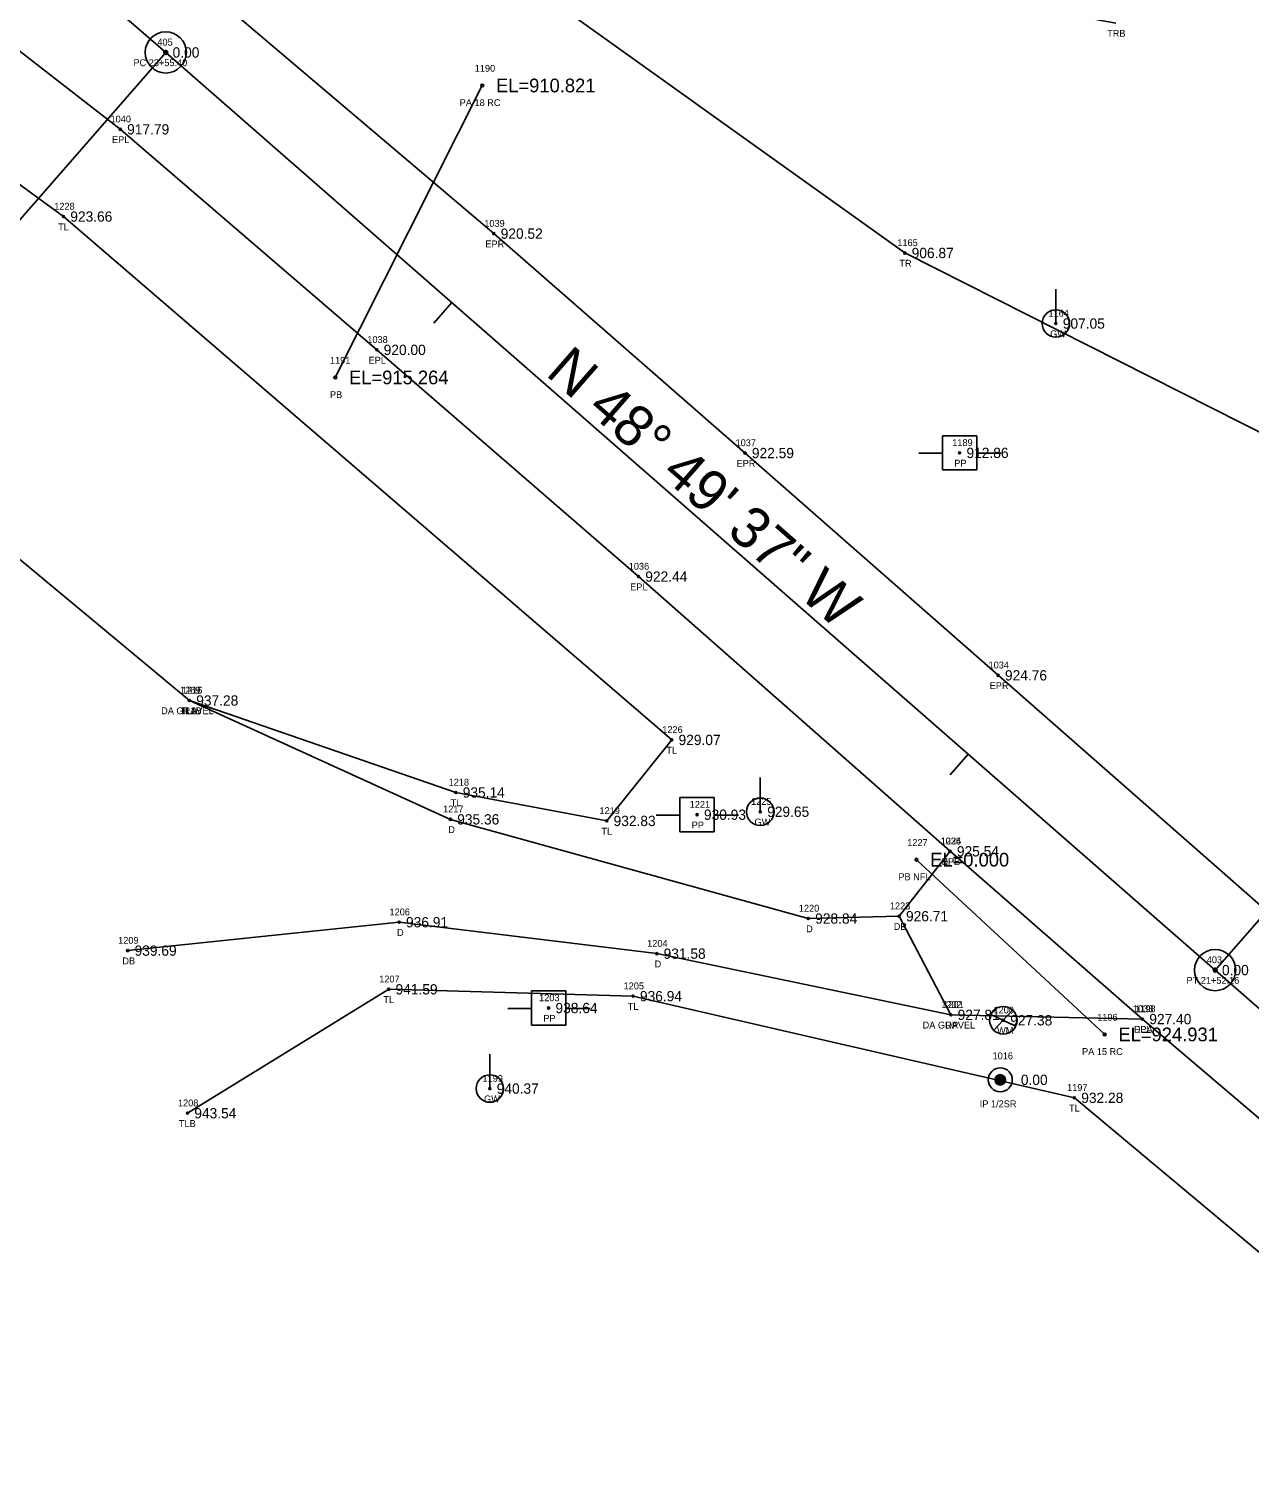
# Model space of a CAD drawing. Extents: x 1393163 to 1398407, y 1072670 to 1074651.
# Drawn here: x 1396870.8 to 1397048.8, y 1074054.9 to 1074266.9 of the extents above; entities that cross this region are included whole.
import ezdxf

# ---------------------------------------------------------------- set-up
doc = ezdxf.new("R2010")
doc.units = 0
for name, color, linetype in [('RD_EX_DR_Pipe', 7, 'Continuous'), ('RD_EX_DR_Pipe_txCode', 7, 'Continuous'), ('RD_EX_Driveway', 7, 'Continuous'), ('RD_EX_Driveway_txCode', 7, 'Continuous'), ('RD_EX_DV_Prop_txCode', 7, 'Continuous'), ('RD_EX_DV_PropPin', 7, 'Continuous'), ('RD_EX_Road', 7, 'Continuous'), ('RD_EX_Road_txCode', 7, 'Continuous'), ('RD_EX_TX_Driveway_ELEV', 7, 'Continuous'), ('RD_EX_TX_DV_Prop_ELEV', 7, 'Continuous'), ('RD_EX_TX_Road_ELEV', 7, 'Continuous'), ('RD_EX_TX_UT_ELEV', 7, 'Continuous'), ('RD_EX_TX_VEG_ELEV', 7, 'Continuous'), ('RD_EX_UT', 7, 'Continuous'), ('RD_EX_UT_txCode', 7, 'Continuous'), ('RD_EX_VEG', 7, 'Continuous'), ('RD_EX_VEG_txCode', 7, 'Continuous'), ('RD_HC_Cl', 7, 'Continuous'), ('RD_HC_Data', 7, 'Continuous'), ('RD_HC_Data_Tic', 7, 'Continuous'), ('RD_HC_Survey_ELEV', 7, 'Continuous'), ('RD_HC_txCode', 7, 'Continuous'), ('RD_SMD_Locator', 7, 'Continuous'), ('RD_TX_Pipe_ElevEX', 7, 'Continuous')]:
    doc.layers.add(name, color=color, linetype=linetype)

msp = doc.modelspace()

# ---------------------------------------------------------------- linework, layer by layer
at = {"layer": 'RD_EX_DR_Pipe'}
for p, q in [((1396936.88, 1074258.65), (1396915.45, 1074216.08)), ((1397027.62, 1074120.29), (1397000.17, 1074145.77))]:
    msp.add_line(p, q, dxfattribs=at)
at = {"layer": 'RD_EX_Driveway'}
for points in [[(1396894.17, 1074168.98), (1396932.22, 1074151.65), (1396984.41, 1074137.19), (1396997.65, 1074137.53)], [(1397033.12, 1074122.53), (1397005.18, 1074123.15), (1396997.65, 1074137.53), (1397005.07, 1074146.99)], [(1397005.18, 1074123.15), (1396962.31, 1074132.07), (1396924.76, 1074136.65), (1396885.18, 1074132.51)]]:
    msp.add_lwpolyline(points, dxfattribs=at)
at = {"layer": 'RD_EX_DV_PropPin'}
for p, q in [((1397011.77, 1074113.24), (1397011.77, 1074114.1)), ((1397011.8, 1074113.19), (1397011.8, 1074114.14)), ((1397011.84, 1074113.15), (1397011.84, 1074114.18)), ((1397011.87, 1074113.12), (1397011.87, 1074114.22)), ((1397011.91, 1074113.09), (1397011.91, 1074114.25)), ((1397011.94, 1074113.06), (1397011.94, 1074114.28)), ((1397011.98, 1074113.03), (1397011.98, 1074114.3)), ((1397012.01, 1074113.01), (1397012.01, 1074114.33)), ((1397012.05, 1074112.99), (1397012.05, 1074114.34)), ((1397012.08, 1074112.98), (1397012.08, 1074114.36)), ((1397012.12, 1074112.96), (1397012.12, 1074114.38)), ((1397012.15, 1074112.95), (1397012.15, 1074114.39)), ((1397012.19, 1074112.94), (1397012.19, 1074114.4)), ((1397012.22, 1074112.93), (1397012.22, 1074114.41)), ((1397012.26, 1074112.92), (1397012.26, 1074114.42)), ((1397012.29, 1074112.92), (1397012.29, 1074114.42)), ((1397012.33, 1074112.91), (1397012.33, 1074114.43)), ((1397012.36, 1074112.91), (1397012.36, 1074114.43)), ((1397012.4, 1074112.91), (1397012.4, 1074114.43)), ((1397012.43, 1074112.91), (1397012.43, 1074114.43)), ((1397012.47, 1074112.91), (1397012.47, 1074114.43)), ((1397012.5, 1074112.92), (1397012.5, 1074114.42)), ((1397012.54, 1074112.92), (1397012.54, 1074114.42)), ((1397012.57, 1074112.93), (1397012.57, 1074114.41)), ((1397012.61, 1074112.94), (1397012.61, 1074114.4)), ((1397012.64, 1074112.95), (1397012.64, 1074114.39)), ((1397012.68, 1074112.96), (1397012.68, 1074114.38)), ((1397012.71, 1074112.98), (1397012.71, 1074114.36)), ((1397012.75, 1074112.99), (1397012.75, 1074114.34)), ((1397012.78, 1074113.01), (1397012.78, 1074114.33)), ((1397012.82, 1074113.03), (1397012.82, 1074114.3)), ((1397012.85, 1074113.06), (1397012.85, 1074114.28)), ((1397012.89, 1074113.09), (1397012.89, 1074114.25)), ((1397012.92, 1074113.12), (1397012.92, 1074114.22)), ((1397012.96, 1074113.15), (1397012.96, 1074114.18)), ((1397012.99, 1074113.19), (1397012.99, 1074114.14)), ((1397013.03, 1074113.24), (1397013.03, 1074114.1)), ((1397011.66, 1074113.47), (1397011.66, 1074113.87)), ((1397011.7, 1074113.37), (1397011.7, 1074113.97)), ((1397011.73, 1074113.3), (1397011.73, 1074114.04)), ((1397013.06, 1074113.3), (1397013.06, 1074114.04)), ((1397013.1, 1074113.37), (1397013.1, 1074113.97)), ((1397013.13, 1074113.47), (1397013.13, 1074113.87))]:
    msp.add_line(p, q, dxfattribs=at)
for radius in [1.75, 0.761]:
    msp.add_circle((1397012.4, 1074113.67), radius, dxfattribs=at)
at = {"layer": 'RD_EX_Road'}
for points in [[(1397127.02, 1074075.08), (1397087.96, 1074107.09), (1397050.33, 1074139.1), (1397012.08, 1074172.65), (1396975.18, 1074205.06), (1396938.56, 1074237.05), (1396899.33, 1074270.29), (1396859.1, 1074302.06), (1396826.71, 1074324.07), (1396788.75, 1074345.97), (1396771.6, 1074353.88), (1396724.53, 1074372.71), (1396674.59, 1074386.64), (1396624.89, 1074395.26)], [(1397113.03, 1074055.78), (1397073.45, 1074088.2), (1397033.12, 1074122.53), (1397005.07, 1074146.99), (1396959.64, 1074187.05), (1396921.5, 1074220.1), (1396884.1, 1074252.26), (1396844.62, 1074282.93), (1396805.23, 1074308.91), (1396761.89, 1074332.05), (1396716.72, 1074350.46), (1396669.99, 1074363.58), (1396621.68, 1074371.65)]]:
    msp.add_lwpolyline(points, dxfattribs=at)
at = {"layer": 'RD_EX_UT'}
for p, q in [((1397020.51, 1074223.94), (1397020.51, 1074228.94)), ((1397008.96, 1074207.59), (1397003.96, 1074207.59)), ((1397003.96, 1074207.59), (1397003.96, 1074202.59)), ((1397008.96, 1074202.59), (1397008.96, 1074207.59)), ((1397000.53, 1074205.03), (1397004, 1074205.03)), ((1397008.89, 1074205.03), (1397012.53, 1074205.03)), ((1397003.96, 1074202.59), (1397008.96, 1074202.59)), ((1396977.41, 1074152.76), (1396977.41, 1074157.76)), ((1396970.68, 1074154.83), (1396965.68, 1074154.83)), ((1396965.68, 1074154.83), (1396965.68, 1074149.83)), ((1396970.68, 1074149.83), (1396970.68, 1074154.83)), ((1396962.25, 1074152.27), (1396965.71, 1074152.27)), ((1396970.61, 1074152.27), (1396974.25, 1074152.27)), ((1396965.68, 1074149.83), (1396970.68, 1074149.83)), ((1396949.04, 1074126.65), (1396944.04, 1074126.65)), ((1396944.04, 1074126.65), (1396944.04, 1074121.65)), ((1396949.04, 1074121.65), (1396949.04, 1074126.65)), ((1396940.61, 1074124.08), (1396944.07, 1074124.08)), ((1396948.96, 1074124.08), (1396952.61, 1074124.08)), ((1397011, 1074123.19), (1397014.63, 1074121.48)), ((1397011.48, 1074120.9), (1397014.15, 1074123.79)), ((1396944.04, 1074121.65), (1396949.04, 1074121.65)), ((1396937.98, 1074112.39), (1396937.98, 1074117.39))]:
    msp.add_line(p, q, dxfattribs=at)
for centre in [(1397020.51, 1074223.94), (1396977.41, 1074152.76), (1397012.84, 1074122.35), (1396937.98, 1074112.39)]:
    msp.add_circle(centre, 2, dxfattribs=at)
at = {"layer": 'RD_EX_VEG'}
for points in [[(1396894.17, 1074168.98), (1396933.03, 1074155.57), (1396955.02, 1074151.42), (1396964.49, 1074163.23), (1396875.81, 1074239.54), (1396798.14, 1074296.2), (1396756.06, 1074318.4), (1396711.3, 1074338.97), (1396669.03, 1074354.22), (1396616.02, 1074355.85)], [(1397153.93, 1074137.81), (1397083.5, 1074191.3), (1396998.48, 1074234.23), (1396876.65, 1074321.33), (1396895.14, 1074321.61), (1397002.52, 1074272.66), (1397029.25, 1074267.76)], [(1396670.41, 1074284.65), (1396674.99, 1074302.45), (1396722.29, 1074311.92), (1396894.17, 1074168.98)], [(1397102.45, 1074044.8), (1397023.2, 1074111.05), (1396958.86, 1074125.87), (1396923.23, 1074126.87), (1396893.89, 1074108.8)]]:
    msp.add_lwpolyline(points, dxfattribs=at)
at = {"layer": 'RD_HC_Cl'}
msp.add_line((1397043.72, 1074129.67), (1396890.73, 1074263.47), dxfattribs=at)
for centre, radius, start, end in [((1396561.57, 1073887.11), 500, 48.8271, 94.0437), ((1398300.81, 1075567), 1909.5, 228.82706, 238.54375)]:
    msp.add_arc(centre, radius, start, end, dxfattribs=at)
at = {"layer": 'RD_HC_Data'}
for p, q in [((1396890.73, 1074263.47), (1396813.91, 1074175.64)), ((1397043.72, 1074129.67), (1397120.06, 1074216.96))]:
    msp.add_line(p, q, dxfattribs=at)
for centre, radius in [((1396890.73, 1074263.47), 3), ((1396890.73, 1074263.47), 0.282), ((1397043.72, 1074129.67), 3), ((1397043.72, 1074129.67), 0.282)]:
    msp.add_circle(centre, radius, dxfattribs=at)
at = {"layer": 'RD_HC_Data_Tic'}
for p, q in [((1396932.43, 1074227), (1396929.8, 1074223.99)), ((1397007.71, 1074161.17), (1397005.07, 1074158.16))]:
    msp.add_line(p, q, dxfattribs=at)
at = {"layer": 'RD_SMD_Locator'}
for centre, radius in [((1396890.73, 1074263.47), 0.15), ((1396936.88, 1074258.65), 0.2), ((1396884.1, 1074252.26), 0.15), ((1396875.81, 1074239.54), 0.15), ((1396938.56, 1074237.05), 0.15), ((1396998.48, 1074234.23), 0.15), ((1397020.51, 1074223.94), 0.15), ((1396921.5, 1074220.1), 0.15), ((1396915.45, 1074216.08), 0.2), ((1396975.18, 1074205.06), 0.15), ((1397006.47, 1074205.08), 0.15), ((1396959.64, 1074187.05), 0.15), ((1397012.08, 1074172.65), 0.15), ((1396894.17, 1074168.98), 0.15), ((1396894.17, 1074168.98), 0.15), ((1396894.17, 1074168.98), 0.15), ((1396964.49, 1074163.23), 0.15), ((1396933.03, 1074155.57), 0.15), ((1396968.19, 1074152.33), 0.15), ((1396977.41, 1074152.76), 0.15), ((1396932.22, 1074151.65), 0.15), ((1396955.02, 1074151.42), 0.15), ((1397000.17, 1074145.77), 0.2), ((1397005.07, 1074146.99), 0.15), ((1397005.07, 1074146.99), 0.15), ((1396997.65, 1074137.53), 0.15), ((1396997.65, 1074137.53), 0.15), ((1396924.76, 1074136.65), 0.15), ((1396984.41, 1074137.19), 0.15), ((1396885.18, 1074132.51), 0.15), ((1396962.31, 1074132.07), 0.15), ((1397043.72, 1074129.67), 0.15), ((1396923.23, 1074126.87), 0.15), ((1396958.86, 1074125.87), 0.15), ((1396946.55, 1074124.14), 0.15), ((1397005.18, 1074123.15), 0.15), ((1397005.18, 1074123.15), 0.15), ((1397033.12, 1074122.53), 0.15), ((1397033.12, 1074122.53), 0.15), ((1397012.84, 1074122.35), 0.15), ((1397027.62, 1074120.29), 0.2), ((1396937.98, 1074112.39), 0.15), ((1397012.4, 1074113.67), 0.15), ((1397023.2, 1074111.05), 0.15), ((1396893.89, 1074108.8), 0.15)]:
    msp.add_circle(centre, radius, dxfattribs=at)

# ---------------------------------------------------------------- texts
at = {"layer": 'RD_EX_DR_Pipe_txCode'}
for s, p in [('1190', (1396935.78, 1074260.65)), ('PA 18 RC', (1396933.59, 1074255.65)), ('1191', (1396914.67, 1074218.08)), ('PB', (1396914.67, 1074213.08)), ('1227', (1396998.83, 1074147.77)), ('PB NFL', (1396997.55, 1074142.77)), ('1196', (1397026.53, 1074122.29)), ('PA 15 RC', (1397024.32, 1074117.29))]:
    msp.add_text(s, height=1, dxfattribs=at).set_placement(p)
at = {"layer": 'RD_EX_Driveway_txCode'}
for s, p in [('1215', (1396893.1, 1074169.98)), ('DA GRAVEL', (1396890.06, 1074166.98)), ('1217', (1396931.16, 1074152.65)), ('D', (1396931.92, 1074149.65)), ('1224', (1397003.73, 1074147.99)), ('DPB', (1397003.82, 1074144.99)), ('1222', (1396996.3, 1074138.53)), ('1223', (1396996.3, 1074138.53)), ('1206', (1396923.35, 1074137.65)), ('1220', (1396983.03, 1074138.19)), ('D', (1396924.45, 1074134.65)), ('D', (1396984.1, 1074135.19)), ('DB', (1396996.87, 1074135.53)), ('DP', (1396996.87, 1074135.53)), ('1209', (1396883.79, 1074133.51)), ('1204', (1396960.92, 1074133.07)), ('DB', (1396884.4, 1074130.51)), ('D', (1396962, 1074130.07)), ('1202', (1397003.79, 1074124.15)), ('1201', (1397004.08, 1074124.15)), ('1198', (1397032.06, 1074123.53)), ('DA GRAVEL', (1397001.08, 1074121.15)), ('DP', (1397004.4, 1074121.15)), ('DPA', (1397031.86, 1074120.53))]:
    msp.add_text(s, height=1, dxfattribs=at).set_placement(p)
at = {"layer": 'RD_EX_DV_Prop_txCode'}
for s, p in [('1016', (1397011.27, 1074116.67)), ('IP 1/2SR', (1397009.41, 1074109.67))]:
    msp.add_text(s, height=1, dxfattribs=at).set_placement(p)
at = {"layer": 'RD_EX_Road_txCode'}
for s, p in [('1040', (1396882.68, 1074253.26)), ('EPL', (1396882.9, 1074250.26)), ('1039', (1396937.17, 1074238.05)), ('EPR', (1396937.33, 1074235.05)), ('1038', (1396920.12, 1074221.1)), ('EPL', (1396920.3, 1074218.1)), ('1037', (1396973.8, 1074206.06)), ('EPR', (1396973.95, 1074203.06)), ('1036', (1396958.23, 1074188.05)), ('EPL', (1396958.44, 1074185.05)), ('1034', (1397010.69, 1074173.65)), ('EPR', (1397010.85, 1074170.65)), ('1035', (1397003.69, 1074147.99)), ('EPL', (1397003.87, 1074144.99)), ('1033', (1397031.74, 1074123.53)), ('EPL', (1397031.92, 1074120.53))]:
    msp.add_text(s, height=1, dxfattribs=at).set_placement(p)
at = {"layer": 'RD_EX_TX_Driveway_ELEV'}
for s, p in [('937.28', (1396895.17, 1074168.23)), ('935.36', (1396933.22, 1074150.9)), ('925.54', (1397006.07, 1074146.24)), ('936.91', (1396925.76, 1074135.9)), ('928.84', (1396985.41, 1074136.44)), ('926.71', (1396998.65, 1074136.78)), ('926.71', (1396998.65, 1074136.78)), ('939.69', (1396886.18, 1074131.76)), ('931.58', (1396963.31, 1074131.32)), ('927.81', (1397006.18, 1074122.4)), ('927.81', (1397006.18, 1074122.4)), ('927.40', (1397034.12, 1074121.78))]:
    msp.add_text(s, height=1.5, dxfattribs=at).set_placement(p)
at = {"layer": 'RD_EX_TX_DV_Prop_ELEV'}
msp.add_text('0.00', height=1.5, dxfattribs=at).set_placement((1397015.4, 1074112.92))
at = {"layer": 'RD_EX_TX_Road_ELEV'}
for s, p in [('917.79', (1396885.1, 1074251.51)), ('920.52', (1396939.56, 1074236.3)), ('920.00', (1396922.5, 1074219.35)), ('922.59', (1396976.18, 1074204.31)), ('922.44', (1396960.64, 1074186.3)), ('924.76', (1397013.08, 1074171.9)), ('925.54', (1397006.07, 1074146.24)), ('927.40', (1397034.12, 1074121.78))]:
    msp.add_text(s, height=1.5, dxfattribs=at).set_placement(p)
at = {"layer": 'RD_EX_TX_UT_ELEV'}
for s, p in [('907.05', (1397021.51, 1074223.19)), ('929.65', (1396978.41, 1074152.01)), ('927.38', (1397013.84, 1074121.6)), ('940.37', (1396938.98, 1074111.64))]:
    msp.add_text(s, height=1.5, dxfattribs=at).set_placement(p)
at = {"layer": 'RD_EX_TX_VEG_ELEV'}
for s, p in [('923.66', (1396876.81, 1074238.79)), ('906.87', (1396999.48, 1074233.48)), ('937.28', (1396895.17, 1074168.23)), ('937.28', (1396895.17, 1074168.23)), ('929.07', (1396965.49, 1074162.48)), ('935.14', (1396934.03, 1074154.82)), ('932.83', (1396956.02, 1074150.67)), ('941.59', (1396924.23, 1074126.12)), ('936.94', (1396959.86, 1074125.12)), ('932.28', (1397024.2, 1074110.3)), ('943.54', (1396894.89, 1074108.05))]:
    msp.add_text(s, height=1.5, dxfattribs=at).set_placement(p)
at = {"layer": 'RD_EX_UT_txCode'}
for s, p in [('1164', (1397019.42, 1074224.94)), ('GW', (1397019.67, 1074221.94)), ('1189', (1397005.4, 1074206.08)), ('PP', (1397005.69, 1074203.08)), ('1225', (1396976.07, 1074153.76)), ('1221', (1396967.12, 1074153.33)), ('PP', (1396967.41, 1074150.33)), ('GW', (1396976.57, 1074150.76)), ('1203', (1396945.16, 1074125.14)), ('PP', (1396945.77, 1074122.14)), ('1200', (1397011.41, 1074123.35)), ('WM', (1397011.93, 1074120.35)), ('1199', (1396936.91, 1074113.39)), ('GW', (1396937.13, 1074110.39))]:
    msp.add_text(s, height=1, dxfattribs=at).set_placement(p)
at = {"layer": 'RD_EX_VEG_txCode'}
for s, p in [('TRB', (1397027.98, 1074265.76)), ('1228', (1396874.47, 1074240.54)), ('TL', (1396875.04, 1074237.54)), ('1165', (1396997.39, 1074235.23)), ('TR', (1396997.69, 1074232.23)), ('1269', (1396892.8, 1074169.98)), ('1216', (1396893.08, 1074169.98)), ('TL1B', (1396892.76, 1074166.98)), ('TLA', (1396892.91, 1074166.98)), ('1226', (1396963.12, 1074164.23)), ('TL', (1396963.72, 1074161.23)), ('1218', (1396931.97, 1074156.57)), ('TL', (1396932.26, 1074153.57)), ('1219', (1396953.96, 1074152.42)), ('TL', (1396954.25, 1074149.42)), ('1207', (1396921.85, 1074127.87)), ('1205', (1396957.48, 1074126.87)), ('TL', (1396922.46, 1074124.87)), ('TL', (1396958.09, 1074123.87)), ('1197', (1397022.14, 1074112.05)), ('1208', (1396892.51, 1074109.8)), ('TL', (1397022.43, 1074109.05)), ('TLB', (1396892.65, 1074106.8))]:
    msp.add_text(s, height=1, dxfattribs=at).set_placement(p)
at = {"layer": 'RD_HC_Data'}
msp.add_text('N 48%%d 49\' 37" W', height=6, rotation=318.8271, dxfattribs=at).set_placement((1396945.96, 1074216.5))
at = {"layer": 'RD_HC_Survey_ELEV'}
for s, p in [('0.00', (1396891.73, 1074262.72)), ('912.86', (1397007.47, 1074204.33)), ('930.93', (1396969.19, 1074151.58)), ('0.00', (1397044.72, 1074128.92)), ('938.64', (1396947.55, 1074123.39))]:
    msp.add_text(s, height=1.5, dxfattribs=at).set_placement(p)
at = {"layer": 'RD_HC_txCode'}
for s, p in [('405', (1396889.51, 1074264.47)), ('PC 23+55.40', (1396886.02, 1074261.47)), ('403', (1397042.5, 1074130.67)), ('PT 21+52.16', (1397039.55, 1074127.67))]:
    msp.add_text(s, height=1, dxfattribs=at).set_placement(p)
at = {"layer": 'RD_TX_Pipe_ElevEX'}
for s, p in [('EL=910.821', (1396938.88, 1074257.65)), ('EL=915.264', (1396917.45, 1074215.08)), ('EL=0.000', (1397002.17, 1074144.77)), ('EL=924.931', (1397029.62, 1074119.29))]:
    msp.add_text(s, height=2, dxfattribs=at).set_placement(p)

doc.saveas('drawing.dxf')
